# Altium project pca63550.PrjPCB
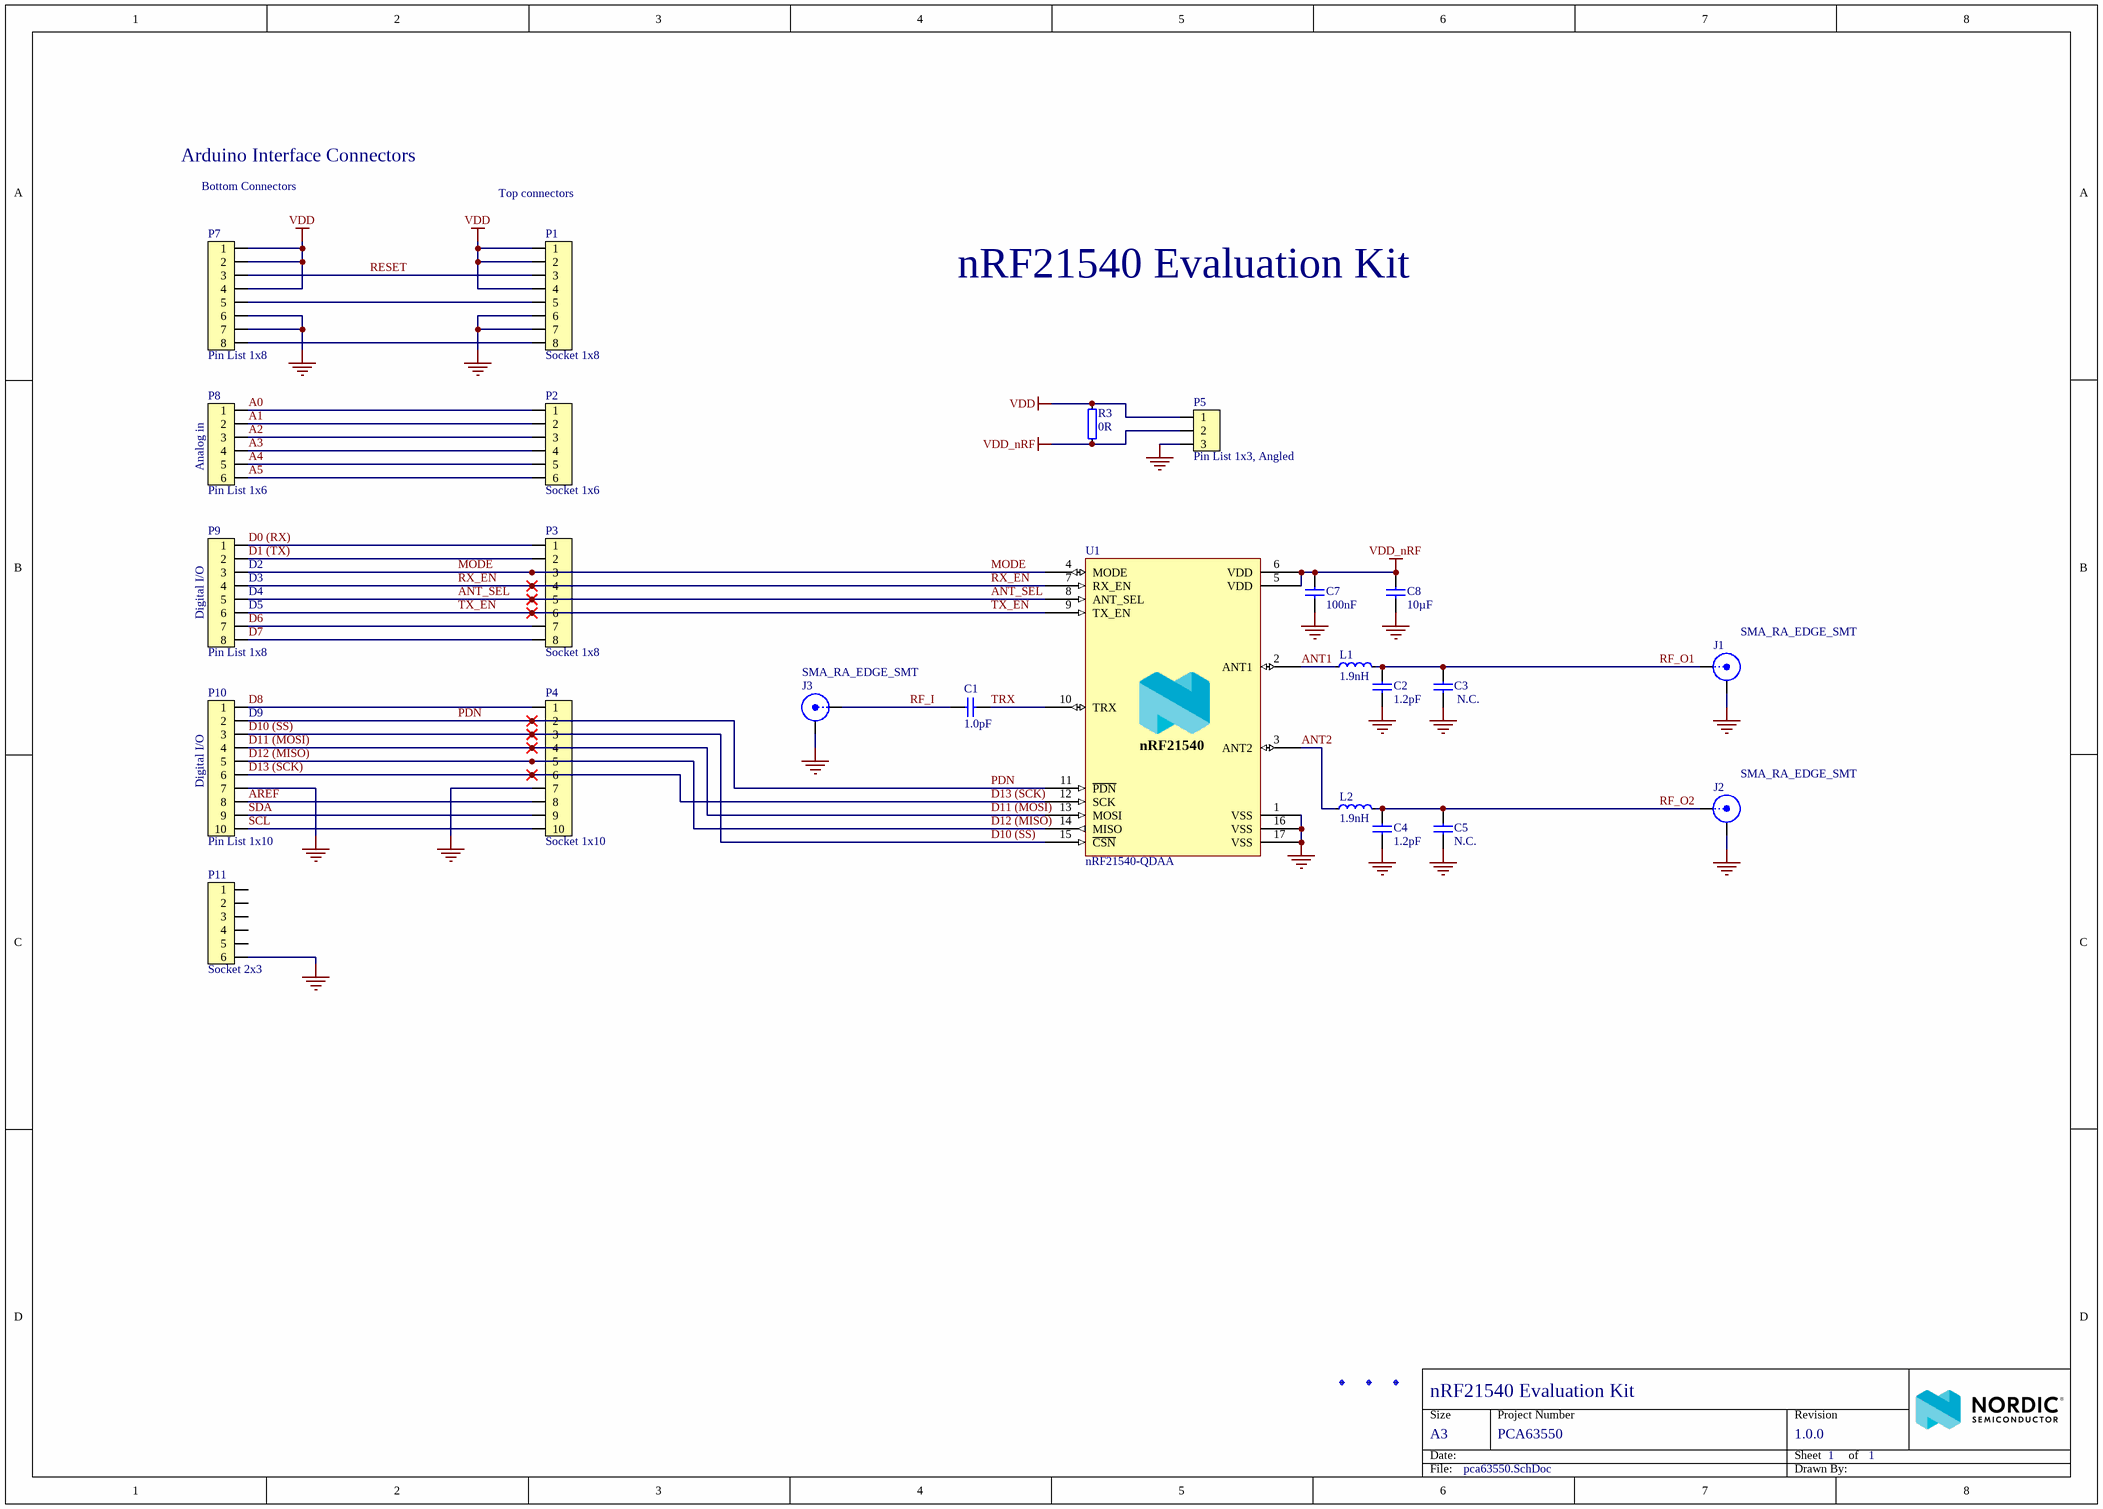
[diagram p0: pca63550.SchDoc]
Author: HANY; BoardThickness: 1.6mm; BoardTitle: nRF21540 Evaluation Kit; NrOfLayers: 4; Organization: Nordic Semiconductor; PCAName: PCA63550; PCBNumber: 400366; PCBRevision: 0018HANY; PCBStackup: 4001 - Free stackup; ProjectName: nRF21540; ProjectNumber: 4446; Revision: 1.0.0; SilkscreenColor: White; SoldermaskColor: Blue; SurfaceFinish: ENIG
1 sheet, 27 parts. Net scope: global (net labels, ports and power ports of the same name join across sheets).
Board file: 400366.PcbDoc

## Sheet pca63550.SchDoc: nRF21540 Evaluation Kit
size A3; Organization: Nordic Semiconductor; Revision: 1.0.0; SheetNumber: 1; SheetTotal: 1; Author: HANY; CompanyName: Nordic Semiconductor; DrawnBy: HANY

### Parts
C1  1.0pF  [CAPC0603X03L_C]
C2  1.2pF  [CAPC0603X03L_C]
C3  N.C.  [CAPC0603X03L_C_NC]
C4  1.2pF  [CAPC0603X03L_C]
C5  N.C.  [CAPC0603X03L_C_NC]
C7  100nF  [CAPC0603X03L_C]
C8  10µF  [CAPC1608X06L]
Fid1  Fiducial mark  [Fiducial]  (value not drawn)  (no BOM)
Fid2  Fiducial mark  [Fiducial]  (value not drawn)  (no BOM)
Fid3  Fiducial mark  [Fiducial]  (value not drawn)  (no BOM)
J1  Part Number: SMA_RA_EDGE_SMT  [SMA_2081005-1]  (hidden comment: SMA_2081005-1)
J2  Part Number: SMA_RA_EDGE_SMT  [SMA_2081005-1]  (hidden comment: SMA_2081005-1)
J3  Part Number: SMA_RA_EDGE_SMT  [SMA_2081005-1]  (hidden comment: SMA_2081005-1)
L1  1.9nH  [INDC0603X03L_C]
L2  1.9nH  [INDC0603X03L_C]
P1  Socket 1x8  [SOCKET_1x8_SMD]
P2  Socket 1x6  [SOCKET_1x6_SMD]
P3  Socket 1x8  [SOCKET_1x8_SMD]
P4  Socket 1x10  [SOCKET_1x10_SMD]
P5  Pin List 1x3, Angled  [LIST_ANG_1x3-SMD-2.54MM]
P7  Pin List 1x8  [LIST_1x8_SMD]
P8  Pin List 1x6  [LIST_1x6_SMD]
P9  Pin List 1x8  [LIST_1x8_SMD]
P10  Pin List 1x10  [LIST_1x10_SMD]
P11  Socket 2x3  [SOCKET_2x3_SMD-2.54mm-bottom]
R3  0R  [RESC1005X04L]
U1  nRF21540-QDAA  [QFN65P400X400X65_HS-17N]

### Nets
GND: C2.1 C3.1 C4.1 C5.1 C7.1 C8.1 J1.2(Y) J2.2(Y) J3.2(Y) P1.6 P1.7 P4.7 P5.3 P7.6 P7.7 P10.7 P11.6 U1.1(VSS) U1.16(VSS) U1.17(VSS)
VDD: P1.1 P1.2 P1.4 P5.1 P7.1 P7.2 P7.4 R3.2
VDD_nRF: C7.2 C8.2 P5.2 R3.1 U1.5(VDD) U1.6(VDD)
A0: P2.1 P8.1
A1: P2.2 P8.2
A2: P2.3 P8.3
A3: P2.4 P8.4
A4: P2.5 P8.5
A5: P2.6 P8.6
ANT1: L1.1 U1.2(ANT1)
ANT2: L2.1 U1.3(ANT2)
ANT_SEL: P3.5 P9.5 U1.8(ANT_SEL)
AREF: P4.8 P10.8
D0 (RX): P3.1 P9.1
D1 (TX): P3.2 P9.2
D6: P3.7 P9.7
D7: P3.8 P9.8
D8: P4.1 P10.1
D10 (SS): P4.3 P10.3 U1.15(~{CSN})
D11 (MOSI): P4.4 P10.4 U1.13(MOSI)
D12 (MISO): P4.5 P10.5 U1.14(MISO)
D13 (SCK): P4.6 P10.6 U1.12(SCK)
MODE: P3.3 P9.3 U1.4(MODE)
PDN: P4.2 P10.2 U1.11(~{PDN})
RESET: P1.3 P7.3
RF_I: C1.1 J3.1(X)
RF_O1: C2.2 C3.2 J1.1(X) L1.2
RF_O2: C4.2 C5.2 J2.1(X) L2.2
RX_EN: P3.4 P9.4 U1.7(RX_EN)
SCL: P4.10 P10.10
SDA: P4.9 P10.9
TRX: C1.2 U1.10(TRX)
TX_EN: P3.6 P9.6 U1.9(TX_EN)
NetP1_5: P1.5 P7.5
NetP1_8: P1.8 P7.8

Not connected (* = marked no-connect by the designer): P11 1 2 3 4 5

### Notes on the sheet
- Arduino Interface Connectors
- Bottom Connectors
- (near P1) Top connectors
- (near P8) Analog in
- (near P9) D2
- (near P9) D3
- (near P9) Digital I/O
- (near P9) D4
- (near P9) D5
- (near P10) D9
- (near P10) Digital I/O

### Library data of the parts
C1 = C0201-1p0: CAP CER 1PF 25V C0G/NP0 0201; Manufacturer: Murata; Manufacturer Part Number: GJM0335C1E1R0BB01D; Note: ±0.1pF; Artikkelnr Noca: N.A.
C2 C4 = C0201-1.2p: Chip Cap 0201; Note: Chip Cap 1%; Artikkelnr Noca: N.A.
C3 C5 = C0201-N.C.: Not mounted; Assembly: Not mounted; Note: Chip Cap; Artikkelnr Noca: N.A.
C7 = C0201-100n: Capacitor, X5R, ±10%; Part number IPS: 00000001248, 00000002505; Note: 16V; Artikkelnr Noca: N.A.
C8 = C0603-10µ: Capacitor, X5R, ±20%; Part number IPS: 00000007785; Note: 6.3V; Artikkelnr Noca: 20039234
Fid1-Fid3 = Fid-Mark: Artikkelnr Noca: N.A.
J1-J3 = SMA_RA_EDGE_SMT: SMA, Female, Right Angle, TH/SMT, 50Ohm, Board Edge; Manufacturer: CompuPack; Manufacturer Part Number: ARFRBE22029-GGP; Artikkelnr Noca: N.A.
L1 L2 = L0201-1n9-HQ-Murata: Inductor, 600mA, ±0.1ｎH, 120mOhm; Manufacturer: Murata; Manufacturer Part Number: LQP03HQ1N9B02; Note: -55°C ~ 125°C; Artikkelnr Noca: N.A.
P1 P3 = Socket 1x8 SMD: Socket 1x8, 2.54mm (100mil), SMD; Manufacturer: W-CON; Manufacturer Part Number: 2171-108MS0CUNR1; Part number IPS: 00000009963; Artikkelnr Noca: 55030002
P2 = Socket 1x6 SMD: Socket 1x6, 2.54mm (100mil), SMD; Manufacturer: W-CON; Manufacturer Part Number: 2171-106MS0CUNR1; Part number IPS: 00000009964; Artikkelnr Noca: 55030001
P4 = Socket 1x10 SMD: Socket 1x10, 2.54mm (100mil), SMD; Manufacturer: W-CON; Manufacturer Part Number: 2171-110MS0CUNR1; Part number IPS: 00000009965; Artikkelnr Noca: 55030004
P5 = Pin List Ang 1x3 SMD, 2.54mm: Pin List 1x3, 2.54mm (100mil), Right Angled, SMD; Manufacturer: W-CON; Manufacturer Part Number: 1125B-1103S0Z135R2; Part number IPS: 00000009971; Artikkelnr Noca: 55010027
P7 P9 = Pin List 1x8 SMD: Pin List 1x8, 2.54mm (100mil), SMD; Manufacturer: W-CON; Manufacturer Part Number: 1125-1108S0M116R2; Part number IPS: N.A.; Artikkelnr Noca: 55010006
P8 = Pin List 1x6 SMD: Pin List 1x6, 2.54mm (100mil), SMD; Manufacturer: W-CON; Manufacturer Part Number: 1125-1106S0M116R2; Part number IPS: N.A.; Artikkelnr Noca: 55010026
P10 = Pin List 1x10 SMD: Pin List 1x10, 2.54mm (100mil), SMD; Manufacturer: W-CON; Manufacturer Part Number: 1125-1110S0M116R2; Part number IPS: N.A.; Artikkelnr Noca: 55010028
P11 = Socket 2x3 SMD Bottom: Socket 2x3, 2.54mm (100mil), SMD; Manufacturer: W-CON; Manufacturer Part Number: 2171-203MS0CUNR1; Part number IPS: N.A.; Artikkelnr Noca: 55030010
R3 = R0402-0R: Resistor, ±5%, 0.063W; Part number IPS: 00000007128; Note: Chip Res 5%; Artikkelnr Noca: 27049000
U1 = nRF21540-QDAA: Radio front-end / range extender for 2.4GHz; Manufacturer: Nordic Semiconductor; Artikkelnr Noca: N.A.

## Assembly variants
Default Variant: not fitted C3 C5 P1 P2 P3 P4 P8 P12 P13 Sh1 Sh2 Sh3 Sh4 Sh5 Sh6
